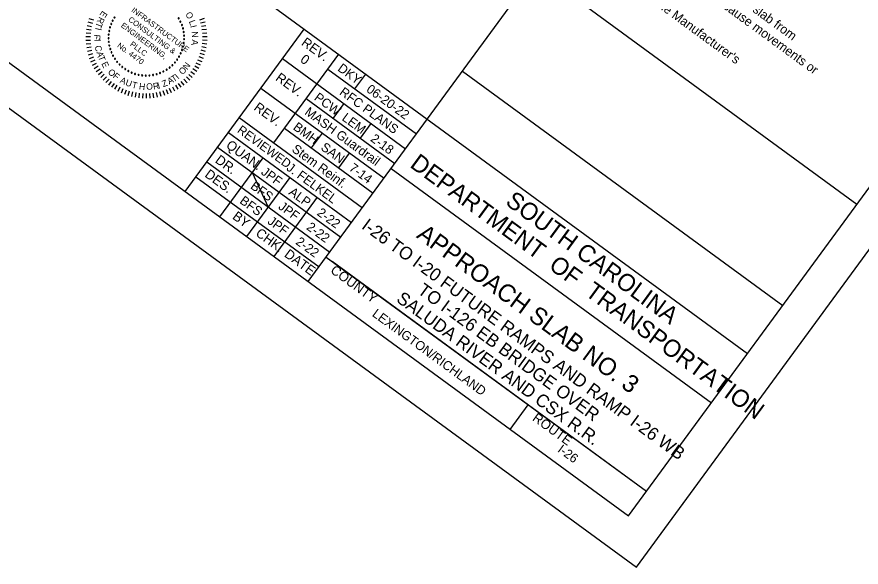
# Model space of a CAD drawing. Extents: x 1970731 to 1970899, y 796145 to 796301.
# Drawn here: x 1970813.63 to 1970859.71, y 796145.21 to 796175.27 of the extents above; entities that cross this region are included whole.
import ezdxf

# ---------------------------------------------------------------- set-up
doc = ezdxf.new("R2010")
doc.units = 0
for name, color, linetype in [('BR_BORDER LINES', 7, 'Continuous'), ('BR_TEXT', 7, 'Continuous'), ('Level 31', 7, 'Continuous')]:
    doc.layers.add(name, color=color, linetype=linetype)

msp = doc.modelspace()

# ---------------------------------------------------------------- linework, layer by layer
at = {"layer": 'BR_BORDER LINES'}
for p, q in [((1970738.359, 796227.562), (1970847.014, 796148.01)), ((1970847.014, 796148.01), (1970896.636, 796215.787)), ((1970811.99, 796187.287), (1970829.306, 796174.609)), ((1970829.532, 796160.81), (1970842, 796177.84)), ((1970842, 796177.84), (1970859.483, 796165.04)), ((1970822.808, 796165.733), (1970829.306, 796174.609)), ((1970829.306, 796174.609), (1970853.513, 796156.886)), ((1970831.189, 796173.23), (1970827.644, 796168.389)), ((1970828.124, 796172.995), (1970834.848, 796168.072)), ((1970830.598, 796172.424), (1970835.439, 796168.879)), ((1970832.077, 796171.341), (1970832.668, 796172.147)), ((1970837.949, 796172.305), (1970855.431, 796159.506)), ((1970826.943, 796171.381), (1970833.667, 796166.458)), ((1970829.416, 796170.81), (1970834.258, 796167.265)), ((1970830.896, 796169.727), (1970831.486, 796170.534)), ((1970825.761, 796169.768), (1970832.485, 796164.845)), ((1970828.235, 796169.196), (1970833.076, 796165.651)), ((1970832.375, 796168.644), (1970832.966, 796169.451)), ((1970825.171, 796168.961), (1970831.895, 796164.038)), ((1970829.714, 796168.113), (1970830.305, 796168.92)), ((1970824.58, 796168.154), (1970831.304, 796163.231)), ((1970831.193, 796167.03), (1970831.784, 796167.837)), ((1970823.989, 796167.347), (1970830.713, 796162.424)), ((1970827.053, 796167.582), (1970824.69, 796164.355)), ((1970834.061, 796166.996), (1970834.061, 796166.996)), ((1970834.061, 796166.996), (1970851.544, 796154.196)), ((1970823.398, 796166.54), (1970830.122, 796161.617)), ((1970828.533, 796166.499), (1970826.17, 796163.272)), ((1970830.012, 796165.416), (1970827.649, 796162.189)), ((1970830.516, 796162.155), (1970847.999, 796149.355)), ((1970830.831, 796161.924), (1970847.999, 796149.355)), ((1970840.559, 796152.736), (1970841.544, 796154.081))]:
    msp.add_line(p, q, dxfattribs=at)
at = {"layer": 'BR_TEXT'}
for p, q in [((1970817.562, 796175.188), (1970817.804, 796175.108)), ((1970823.847, 796175.183), (1970823.605, 796175.102)), ((1970817.458, 796174.798), (1970817.708, 796174.748)), ((1970817.504, 796174.995), (1970817.75, 796174.93)), ((1970823.905, 796174.989), (1970823.659, 796174.924)), ((1970823.95, 796174.792), (1970823.701, 796174.742)), ((1970817.403, 796174.399), (1970817.657, 796174.379)), ((1970817.424, 796174.599), (1970817.677, 796174.565)), ((1970823.984, 796174.593), (1970823.732, 796174.558)), ((1970824.005, 796174.392), (1970823.751, 796174.373)), ((1970817.393, 796174.197), (1970817.648, 796174.193)), ((1970817.396, 796173.995), (1970817.651, 796174.007)), ((1970817.411, 796173.794), (1970817.665, 796173.821)), ((1970823.995, 796173.787), (1970823.742, 796173.814)), ((1970824.011, 796173.989), (1970823.756, 796174)), ((1970824.014, 796174.191), (1970823.76, 796174.187)), ((1970817.439, 796173.593), (1970817.69, 796173.636)), ((1970817.478, 796173.395), (1970817.726, 796173.453)), ((1970823.928, 796173.389), (1970823.68, 796173.447)), ((1970823.968, 796173.587), (1970823.716, 796173.63)), ((1970817.53, 796173.2), (1970817.774, 796173.273)), ((1970817.593, 796173.009), (1970817.833, 796173.096)), ((1970817.668, 796172.821), (1970817.902, 796172.923)), ((1970823.737, 796172.815), (1970823.503, 796172.917)), ((1970823.812, 796173.003), (1970823.573, 796173.09)), ((1970823.876, 796173.194), (1970823.632, 796173.267)), ((1970817.755, 796172.638), (1970817.981, 796172.754)), ((1970817.852, 796172.461), (1970818.071, 796172.591)), ((1970817.96, 796172.291), (1970818.171, 796172.433)), ((1970823.444, 796172.286), (1970823.233, 796172.428)), ((1970823.552, 796172.456), (1970823.333, 796172.586)), ((1970823.65, 796172.633), (1970823.423, 796172.749)), ((1970818.078, 796172.127), (1970818.28, 796172.282)), ((1970818.206, 796171.971), (1970818.397, 796172.138)), ((1970818.343, 796171.822), (1970818.524, 796172.001)), ((1970823.06, 796171.818), (1970822.879, 796171.997)), ((1970823.198, 796171.966), (1970823.006, 796172.133)), ((1970823.326, 796172.122), (1970823.124, 796172.277)), ((1970818.489, 796171.683), (1970818.659, 796171.872)), ((1970818.643, 796171.552), (1970818.801, 796171.752)), ((1970818.804, 796171.431), (1970818.95, 796171.64)), ((1970818.973, 796171.321), (1970819.106, 796171.538)), ((1970822.429, 796171.317), (1970822.296, 796171.535)), ((1970822.598, 796171.428), (1970822.452, 796171.637)), ((1970822.76, 796171.548), (1970822.601, 796171.748)), ((1970822.914, 796171.679), (1970822.744, 796171.868)), ((1970819.149, 796171.22), (1970819.268, 796171.445)), ((1970819.33, 796171.131), (1970819.435, 796171.363)), ((1970819.516, 796171.053), (1970819.607, 796171.291)), ((1970819.707, 796170.986), (1970819.783, 796171.229)), ((1970819.901, 796170.931), (1970819.962, 796171.178)), ((1970820.098, 796170.888), (1970820.144, 796171.139)), ((1970820.298, 796170.857), (1970820.329, 796171.11)), ((1970820.499, 796170.839), (1970820.514, 796171.093)), ((1970820.701, 796170.832), (1970820.701, 796171.087)), ((1970820.902, 796170.838), (1970820.887, 796171.093)), ((1970821.104, 796170.857), (1970821.072, 796171.109)), ((1970821.303, 796170.887), (1970821.257, 796171.138)), ((1970821.501, 796170.93), (1970821.439, 796171.177)), ((1970821.695, 796170.984), (1970821.618, 796171.227)), ((1970821.886, 796171.051), (1970821.795, 796171.288)), ((1970822.072, 796171.128), (1970821.967, 796171.36)), ((1970822.253, 796171.217), (1970822.134, 796171.442))]:
    msp.add_line(p, q, dxfattribs=at)
for centre, start, end in [((1970818.957, 796175.242), 57.4713, 237.4713), ((1970818.957, 796175.242), 237.4713, 57.4713), ((1970822.462, 796175.193), 121.1636, 301.1636), ((1970822.462, 796175.193), 301.1636, 121.1636), ((1970818.712, 796174.699), 74.0866, 254.0866), ((1970818.712, 796174.699), 254.0866, 74.0866), ((1970818.776, 796174.888), 68.5482, 248.5482), ((1970818.776, 796174.888), 248.5482, 68.5482), ((1970818.858, 796175.069), 63.0097, 243.0097), ((1970818.858, 796175.069), 243.0097, 63.0097), ((1970822.556, 796175.018), 115.6251, 295.6251), ((1970822.556, 796175.018), 295.6251, 115.6251), ((1970822.633, 796174.834), 110.0866, 290.0866), ((1970822.633, 796174.834), 290.0866, 110.0866), ((1970818.639, 796174.308), 85.1636, 265.1636), ((1970818.639, 796174.308), 265.1636, 85.1636), ((1970818.666, 796174.505), 79.6251, 259.6251), ((1970818.666, 796174.505), 259.6251, 79.6251), ((1970822.692, 796174.644), 104.5482, 284.5482), ((1970822.692, 796174.644), 284.5482, 104.5482), ((1970822.732, 796174.449), 99.0097, 279.0097), ((1970822.754, 796174.25), 93.4713, 273.4713), ((1970822.732, 796174.449), 279.0097, 99.0097), ((1970822.754, 796174.25), 273.4713, 93.4713), ((1970818.632, 796174.108), 90.702, 270.702), ((1970818.643, 796173.909), 96.2405, 276.2405), ((1970818.632, 796174.108), 270.702, 90.702), ((1970818.643, 796173.909), 276.2405, 96.2405), ((1970822.738, 796173.852), 82.3943, 262.3943), ((1970822.756, 796174.051), 87.9328, 267.9328), ((1970822.738, 796173.852), 262.3943, 82.3943), ((1970822.756, 796174.051), 267.9328, 87.9328), ((1970818.674, 796173.712), 101.779, 281.779), ((1970818.674, 796173.712), 281.779, 101.779), ((1970818.724, 796173.519), 107.3174, 287.3174), ((1970818.724, 796173.519), 287.3174, 107.3174), ((1970818.792, 796173.332), 112.8559, 292.8559), ((1970818.792, 796173.332), 292.8559, 112.8559), ((1970822.574, 796173.279), 65.779, 245.779), ((1970822.574, 796173.279), 245.779, 65.779), ((1970822.647, 796173.465), 71.3174, 251.3174), ((1970822.647, 796173.465), 251.3174, 71.3174), ((1970822.702, 796173.656), 76.8559, 256.8559), ((1970822.702, 796173.656), 256.8559, 76.8559), ((1970818.878, 796173.152), 118.3943, 298.3943), ((1970818.878, 796173.152), 298.3943, 118.3943), ((1970818.981, 796172.981), 123.9328, 303.9328), ((1970818.981, 796172.981), 303.9328, 123.9328), ((1970819.099, 796172.821), 129.4713, 309.4713), ((1970819.099, 796172.821), 309.4713, 129.4713), ((1970822.376, 796172.934), 54.702, 234.702), ((1970822.376, 796172.934), 234.702, 54.702), ((1970822.483, 796173.102), 60.2405, 240.2405), ((1970822.483, 796173.102), 240.2405, 60.2405), ((1970819.233, 796172.674), 135.0097, 315.0097), ((1970819.233, 796172.674), 315.0097, 135.0097), ((1970819.38, 796172.539), 140.5482, 320.5482), ((1970819.38, 796172.539), 320.5482, 140.5482), ((1970819.54, 796172.42), 146.0866, 326.0866), ((1970819.54, 796172.42), 326.0866, 146.0866), ((1970821.801, 796172.388), 32.5482, 212.5482), ((1970821.801, 796172.388), 212.5482, 32.5482), ((1970821.964, 796172.503), 38.0866, 218.0866), ((1970821.964, 796172.503), 218.0866, 38.0866), ((1970822.115, 796172.633), 43.6251, 223.6251), ((1970822.115, 796172.633), 223.6251, 43.6251), ((1970822.252, 796172.778), 49.1636, 229.1636), ((1970822.252, 796172.778), 229.1636, 49.1636), ((1970819.71, 796172.316), 151.6251, 331.6251), ((1970819.71, 796172.316), 331.6251, 151.6251), ((1970819.89, 796172.23), 157.1636, 337.1636), ((1970819.89, 796172.23), 337.1636, 157.1636), ((1970820.077, 796172.161), 162.702, 342.702), ((1970820.077, 796172.161), 342.702, 162.702), ((1970820.27, 796172.111), 348.2405, 168.2405), ((1970820.27, 796172.111), 168.2405, 348.2405), ((1970820.467, 796172.079), 353.779, 173.779), ((1970820.467, 796172.079), 173.779, 353.779), ((1970820.666, 796172.067), 359.3174, 179.3174), ((1970820.666, 796172.067), 179.3174, 359.3174), ((1970820.865, 796172.074), 4.8559, 184.8559), ((1970820.865, 796172.074), 184.8559, 4.8559), ((1970821.062, 796172.1), 10.3943, 190.3943), ((1970821.062, 796172.1), 190.3943, 10.3943), ((1970821.257, 796172.145), 15.9328, 195.9328), ((1970821.257, 796172.145), 195.9328, 15.9328), ((1970821.446, 796172.208), 21.4713, 201.4713), ((1970821.446, 796172.208), 201.4713, 21.4713), ((1970821.627, 796172.29), 27.0097, 207.0097), ((1970821.627, 796172.29), 207.0097, 27.0097)]:
    msp.add_arc(centre, 0.028, start, end, dxfattribs=at)
at = {"layer": 'Level 31'}
for p, q in [((1970826.463, 796166.775), (1970827.351, 796164.885)), ((1970841.763, 796159.175), (1970841.763, 796159.175))]:
    msp.add_line(p, q, dxfattribs=at)
msp.add_lwpolyline([(1970731.261, 796230.28), (1970847.449, 796145.214), (1970899.434, 796216.218), (1970783.245, 796301.284)], close=True, dxfattribs=at)

# ---------------------------------------------------------------- texts
at = {"layer": 'BR_TEXT'}
for s, height, rotation, p in [('Take all necessary precautions to protect the sleeper slab from', 0.49995, 323.7906, (1970840.943, 796184.954)), ('temporary loadings or any condition which could cause movements or', 0.49995, 323.7906, (1970840.471, 796184.309)), ("Set this dimension in accordance with the Manufacturer's", 0.49995, 323.7906, (1970839.254, 796182.646)), ('E', 0.349, 236.8156, (1970818.304, 796175.633)), ('INFRASTRUCTURE', 0.29909, 323.3174, (1970819.852, 796175.586)), ('R', 0.349, 242.8156, (1970818.127, 796175.305)), ('CONSULTING &', 0.29909, 323.3174, (1970819.681, 796175.073)), ('O', 0.349, 301.4286, (1970822.809, 796175.419)), ('T', 0.349, 248.8156, (1970817.997, 796175.01)), ('ENGINEERING,', 0.29909, 323.3174, (1970819.277, 796174.748)), ('L', 0.349, 290.8986, (1970823.009, 796175.022)), ('I', 0.349, 283.3686, (1970823.089, 796174.776)), ('F', 0.349, 263.5619, (1970817.85, 796174.329)), ('I', 0.349, 257.5619, (1970817.921, 796174.704)), ('N', 0.349, 274.3386, (1970823.166, 796174.468)), ('I', 0.349, 272.3174, (1970817.859, 796174.055)), ('No. 4470', 0.2991, 323.3174, (1970819.079, 796173.651)), ('PLLC', 0.2991, 323.3174, (1970819.773, 796173.722)), ('A', 0.349, 265.3085, (1970823.181, 796174.049)), ('REV.', 0.52, 323.7906, (1970829.114, 796173.773)), ('C', 0.349, 278.3174, (1970817.885, 796173.689)), ('A', 0.349, 284.3174, (1970817.969, 796173.336)), ('T', 0.349, 290.3174, (1970818.054, 796173.084)), ('E', 0.349, 296.3174, (1970818.227, 796172.72)), ('0', 0.52, 323.7906, (1970829.052, 796172.851)), ('O', 0.349, 314.3174, (1970818.564, 796172.231)), ('O', 0.349, 46.9991, (1970822.677, 796172.086)), ('N', 0.349, 52.9991, (1970822.929, 796172.355)), ('DKY', 0.5, 323.7906, (1970831.095, 796172.369)), ('F', 0.349, 320.3174, (1970818.838, 796171.986)), ('A', 0.349, 334.3174, (1970819.221, 796171.697)), ('A', 0.349, 27.186, (1970821.944, 796171.572)), ('T', 0.349, 33.186, (1970822.186, 796171.694)), ('I', 0.349, 41.6998, (1970822.428, 796171.851)), ('REV.', 0.52, 323.7906, (1970827.702, 796171.844)), ('U', 0.349, 340.3174, (1970819.523, 796171.542)), ('T', 0.349, 346.3174, (1970819.877, 796171.404)), ('H', 0.349, 352.3174, (1970820.276, 796171.319)), ('O', 0.349, 2.3174, (1970820.693, 796171.291)), ('R', 0.349, 8.3174, (1970821.082, 796171.304)), ('I', 0.349, 16.1245, (1970821.353, 796171.34)), ('Z', 0.349, 21.186, (1970821.622, 796171.429)), ('06-20-22', 0.5, 323.7906, (1970832.659, 796171.224)), ('PCW', 0.5, 323.7906, (1970829.813, 796170.774)), ('RFC PLANS', 0.5, 323.7906, (1970831.193, 796171.07)), ('REV.', 0.52, 323.7906, (1970826.52, 796170.23)), ('MASH Guardrail', 0.5, 323.7906, (1970829.297, 796169.984)), ('LEM', 0.5, 323.7906, (1970831.33, 796169.663)), ('REVIEWED', 0.48, 323.7906, (1970825.615, 796168.999)), ('BMH', 0.5, 323.7906, (1970828.664, 796169.159)), ('2-18', 0.5, 323.7906, (1970832.888, 796168.523)), ('QUAN.', 0.52, 323.7906, (1970825.003, 796168.167)), ('Stem Reinf.', 0.5, 323.7906, (1970828.594, 796167.954)), ('SAN', 0.5, 323.7906, (1970830.173, 796168.054)), ('DEPARTMENT  OF  TRANSPORTATION', 0.94348, 323.7906, (1970835.027, 796167.102)), ('DR.', 0.52, 323.7906, (1970824.409, 796167.355)), ('7-14', 0.5, 323.7906, (1970831.717, 796166.924)), ('DES.', 0.52, 323.7906, (1970823.842, 796166.573)), ('JPF', 0.5, 323.7906, (1970826.915, 796166.715)), ('J. FELKEL', 0.5, 323.7906, (1970828.302, 796166.938)), ('BFS', 0.5, 323.7906, (1970826.335, 796165.939)), ('BFS', 0.5, 323.7906, (1970825.746, 796165.135)), ('ALP', 0.5, 323.7906, (1970828.424, 796165.61)), ('SOUTH CAROLINA', 0.94348, 323.7906, (1970840.238, 796165.06)), ('JPF', 0.5, 323.7906, (1970827.859, 796164.823)), ('BY', 0.52, 323.7906, (1970825.353, 796164.276)), ('2-22', 0.5, 323.7906, (1970829.968, 796164.48)), ('JPF', 0.5, 323.7906, (1970827.27, 796164.019)), ('I-26 TO I-20 FUTURE RAMPS AND RAMP I-26 WB', 0.7, 323.7906, (1970832.393, 796163.747)), ('CHK.', 0.52, 323.7906, (1970826.618, 796163.357)), ('2-22', 0.5, 323.7906, (1970829.395, 796163.699)), ('APPROACH SLAB NO. 3', 0.96, 323.7906, (1970835.388, 796163.248)), ('2-22', 0.5, 323.7906, (1970828.807, 796162.894)), ('DATE', 0.52, 323.7906, (1970828.184, 796162.21)), ('COUNTY', 0.52, 323.7906, (1970830.697, 796161.337)), ('TO I-126 EB BRIDGE OVER', 0.7, 323.7906, (1970835.446, 796160.211)), ('SALUDA RIVER AND CSX R.R.', 0.7, 323.7906, (1970834.29, 796159.755)), ('LEXINGTON/RICHLAND', 0.49998, 323.7906, (1970832.982, 796158.959)), ('ROUTE', 0.52, 323.7906, (1970841.724, 796153.263)), ('I-26', 0.5, 323.7906, (1970843.104, 796151.549))]:
    msp.add_text(s, height=height, rotation=rotation, dxfattribs=at).set_placement(p)

doc.saveas('drawing.dxf')
